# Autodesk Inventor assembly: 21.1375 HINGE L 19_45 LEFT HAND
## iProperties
Created: 2007-01
Part Number: 21.1375 HINGE L 19_45 LEFT HAND
Document SubType Name: Assembly
Designer: Andy Moles
Author: Andy Moles
